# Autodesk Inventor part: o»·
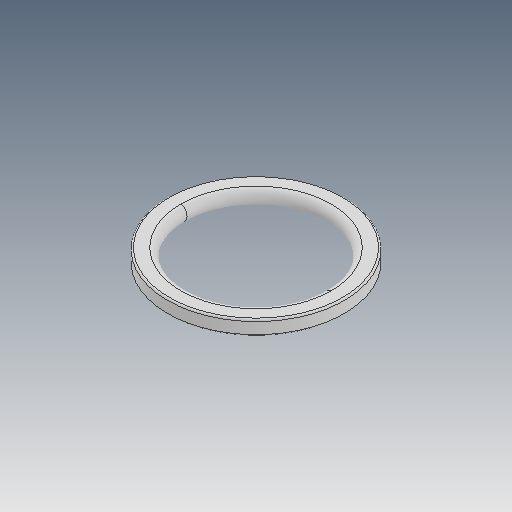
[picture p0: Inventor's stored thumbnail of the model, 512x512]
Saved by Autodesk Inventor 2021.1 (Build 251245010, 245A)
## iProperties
Created: 2014-12
Part Number: o»·
Material: Ogólny
Document SubType Name: Modeling
Designer: user
Density: 1 g/cm^3
Appearance: Domyślna
Author: user
Revision Number: ÈÎºÎ
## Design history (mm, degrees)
feature "ÊäÈë1"
node "Bryła1"
